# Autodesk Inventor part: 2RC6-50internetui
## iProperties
Created: 2010-11
Part Number: 2RC6-50internetui
Document SubType Name: Modeling
Designer: Darius
Author: Darius
Translation Standard: STEP AP203
File Name: 2RC6-50.STEP
Preprocessor: SolidWorks 2003240
Postprocessor: Build: 272, Release: 10 SP3a - Date: Thu 12/15/2005
Sent Units: MILLIMETERS
Uncertainty: 1e-05
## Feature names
1. Base1
